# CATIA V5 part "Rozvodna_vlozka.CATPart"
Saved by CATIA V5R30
Part number: Rozvodna_vlozka
Definition: EH 6304_20_12_1
Nomenclature: EH 6304_20_12_1
Source: Unknown
Description: PART--DESC
Bounding box of the stored display mesh (mm): x 79.5 to 135.2, y -11 to 11, z 56.71 to 78.69
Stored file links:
  E:\Bakalarka\Model\Forma_v7\Rozvodna_vlozka.CATPart
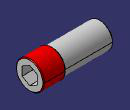
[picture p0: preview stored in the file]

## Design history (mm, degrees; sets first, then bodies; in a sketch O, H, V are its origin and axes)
Body1 "MANIFOLD_SOLID_BREP #3738" (main body)
  Solid1: solid without history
